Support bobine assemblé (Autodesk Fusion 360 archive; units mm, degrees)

design "Support bobine assemblé" references "Support bobine flanc gauche", "Support bobine flanc droit", "Support bobine base"
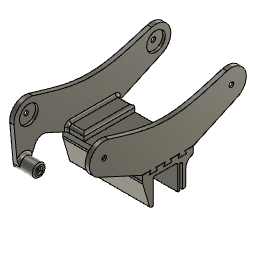
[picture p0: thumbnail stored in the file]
component_insert "Insertion d'un composant1"
component_insert "Insertion d'un composant2"
component_insert "Insertion d'un composant3"
joint "Assembler4" alignAngle 0 alignOffsetX 0 alignOffsetY 0 alignOffsetZ 0
joint "Assembler6" alignAngle 0 alignOffsetX 0 alignOffsetY 0 alignOffsetZ 0

design "Support bobine base"
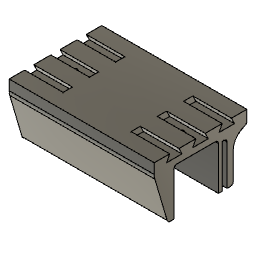
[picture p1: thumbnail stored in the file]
sketch "Esquisse1" plane through (0, 0, 0) normal (1, 0, 0) x axis (0, 1, 0)
  line L1 (21.2, 38) -> (-21.2, 38)
  line L2 (17.2, 0) -> (21.2, 0)
  line L3 (17.2, 28) -> (17.2, 0)
  line L4 (14, 0) -> (14, 28)
  line L5 (11.6, 0) -> (14, 0)
  line L6 (11.6, 30) -> (11.6, 0)
  line L7 (-17.2, 0) -> (-17.2, 30)
  line L8 (-21.2, 0) -> (-17.2, 0)
  line L9 (-21.2, 38) -> (-21.2, 0)
  line L10 (21.2, 38) -> (21.2, 0)
  line L11 (11.6, 30) -> (-17.2, 30)
  line L12 (17.2, 28) -> (14, 28)
  line L13 (-30, 38) -> (-21.2, 38)
  line L14 (30, 38) -> (21.2, 38)
  line L15 (27, 26) -> (21.2, 26)
  line L16 (30, 30) -> (30, 38)
  line L17 (21.2, 26) -> (30, 30)
  line L18 (-30, 30) -> (-30, 38)
  line L19 (-21.2, 0) -> (-30, 30)
  point P3 (21.2, 38)
  point P14 (21.2, 38)
  point P17 (21.2, 26)
  point P11 (-17.2, 30)
  point P12 (-17.2, 0)
  point P2 (-21.2, 38)
  point P13 (-21.2, 0)
  point P8 (14, 0)
  point P9 (11.6, 0)
  point P4 (21.2, 0)
  point P5 (17.2, 0)
  point P1 (0, 0)
  point P6 (17.2, 28)
  point P7 (14, 28)
  point P10 (11.6, 30)
  point P15 (-30, 38)
  point P16 (30, 38)
  point P19 (30, 30)
  point P20 (-30, 30)
  collinear L5 L8
  collinear L2 L8
  horizontal L1
  perpendicular L7 L11
  perpendicular L3 L12
  perpendicular L6 L11
  perpendicular L1 L9
  perpendicular L1 L10
  perpendicular L4 L12
  perpendicular L2 L10
  perpendicular L2 L3
  coincident P3 P14
  perpendicular L9 L13
  perpendicular L10 L14
  coincident L10 P17
  perpendicular L10 L15
  perpendicular L11 L18
  perpendicular L14 L16
  dimension "d3" distance P11 P12 = 30
  dimension "d4" distance P2 P13 = 38
  dimension "d5" distance P12 P13 = 4
  dimension "d6" distance P8 P9 = 2.4
  dimension "d7" distance P4 P5 = 4
  dimension "d8" distance P2 P3 = 42.4
  dimension "d9" distance P1 L1 = 38
  dimension "d10" distance P6 P7 = 3.2
  dimension "d11" distance P10 P11 = 28.8
  dimension "d12" distance P1 P13 = 21.2
  dimension "d21" distance P1 L12 = 28
  dimension "d24" distance P2 P15 = 8.8
  dimension "d25" distance P14 P16 = 8.8
  dimension "d26" distance L14 L15 = 12
  dimension "d59" distance L14 P19 = 8
  dimension "d64" distance P15 P20 = 8
extrude "Extrusion1" new body sketch "Esquisse1" profile of L1 L2 L3 L4 L5 L6 L7 L8 L9 L10 L11 L12 L13 L14 L16 L17 L18 L19 distance 47
sketch "Esquisse3" plane through (0, 11.6, 0) normal (0, -1, 0) x axis (1, 0, 0)
  line L1 (5, -2) -> (5, 30)
  line L2 (-33, -2) -> (-33, 30)
  line L3 (-47, -2) -> (-47, 30)
  line L4 (-33, 30) -> (-47, 30)
  line L5 (5, 30) -> (-14, 30)
  line L6 (-33, -2) -> (-47, -2)
  line L7 (5, -2) -> (-14, -2)
  line L8 (-14, -2) -> (-14, 30)
  line L9 (47, 38) -> (-47, 38)
  line L10 (-47, 0) -> (47, 0)
  line L11 (47, 0) -> (47, 30)
  line L12 (47, 30) -> (-47, 30)
  line L13 (47, 38) -> (47, 30)
  line L14 (-47, 38) -> (47, 38)
  line L15 (-47, 30) -> (-47, 38)
  line L16 (47, 0) -> (-47, 0)
  line L17 (47, 30) -> (47, 0)
  line L18 (-47, 30) -> (47, 30)
  line L19 (-47, 0) -> (-47, 30)
  point P3 (-14, 30)
  point P9 (-14, -2)
  point P6 (5, -2)
  point P8 (-33, -2)
  point P7 (-47, -2)
  coincident P3 L4
  perpendicular L2 L4
  perpendicular L3 L4
  perpendicular L1 L6
  coincident P9 L6
  collinear L4 L5
  collinear L6 L7
  perpendicular L7 L8
  dimension "d38" distance P6 P9 = 19
  dimension "d39" distance P8 P9 = 19
  dimension "d40" distance L4 L6 = 32
  dimension "d65" distance L4 L14 = 8
  dimension "d66" distance L1 L17 = 42
  dimension "d67" distance P7 P8 = 14
extrude "Extrusion2" cut sketch "Esquisse3" profile of L5 L1 L2 L3 L7 to an object
sketch "Esquisse5" plane through (0, 0, 0) normal (1, 0, 0) x axis (0, 1, 0)
  line L1 (21.2, 22.7263) -> (21.2, 2)
  line L2 (30, 38) -> (23.136, 28.6399)
  line L3 (-30, 38) -> (30, 38)
  line L4 (-21.5587, 1.5488) -> (-30, 38)
  line L5 (-17.2, 0) -> (-19.6102, 0)
  line L6 (-17.2, 28) -> (-17.2, 0)
  line L7 (9.6, 30) -> (-15.2, 30)
  line L8 (11.6, 0) -> (11.6, 28)
  line L9 (14, 0) -> (11.6, 0)
  line L10 (14, 28) -> (14, 0)
  line L11 (15.2, 28) -> (14, 28)
  line L12 (17.2, 0) -> (17.2, 26)
  line L13 (19.2, 0) -> (17.2, 0)
  line L14 (0, 38) -> (0, 0)
  line L15 (30, 34) -> (-30, 34)
  line L16 (-30, 38) -> (30, 38)
  line L17 (-3, 38) -> (-5, 34)
  line L18 (3, 38) -> (5, 34)
  line L19 (3, 38) -> (-3, 38)
  line L20 (5, 34) -> (-5, 34)
  line L21 (-20, 38) -> (-22, 34)
  line L22 (-14, 38) -> (-12, 34)
  line L23 (-12, 34) -> (-22, 34)
  line L24 (-14, 38) -> (-20, 38)
  line L25 (14, 38) -> (12, 34)
  line L26 (20, 38) -> (22, 34)
  line L27 (22, 34) -> (12, 34)
  line L28 (20, 38) -> (14, 38)
  line L29 (30, 38) -> (-30, 38)
  line L30 (-29.0737, 34) -> (27.0667, 34)
  arc A1 centre (19.2, 2) radius 2 clockwise from (21.2, 2) to (19.2, 0)
  arc A2 centre (31.2, 22.7263) radius 10 clockwise from (21.2, 22.7263) to (23.136, 28.6399)
  arc A3 centre (-19.6102, 2) radius 2 clockwise from (-19.6102, 0) to (-21.5587, 1.5488)
  arc A4 centre (-15.2, 28) radius 2 clockwise from (-17.2, 28) to (-15.2, 30)
  arc A5 centre (9.6, 28) radius 2 clockwise from (9.6, 30) to (11.6, 28)
  arc A6 centre (15.2, 26) radius 2 clockwise from (15.2, 28) to (17.2, 26)
  point P1 (0, 0)
  point P27 (0, 0)
  point P29 (-30, 34)
  point P32 (-30, 38)
  point P28 (0, 38)
  point P33 (-5, 34)
  point P34 (-3, 38)
  point P35 (5, 34)
  point P36 (3, 38)
  point P47 (27.0667, 34)
  point P48 (-29.0737, 34)
  coincident P1 P27
  perpendicular L3 L14
  horizontal L15
  equal L3 L15
  vertical P29 P32
  coincident P28 L16
  coincident L15 P33
  coincident L16 P34
  symmetric L14 P33 P35
  symmetric L14 P34 P36
  coincident L2 P47
  coincident L15 P47
  coincident L15 P48
  coincident L4 P48
  dimension "d48" distance L15 L16 = 4
  dimension "d50" distance P28 P34 = 3
  dimension "d51" distance P28 P33 = 5
  dimension "d54" R-Pattern1-uDistance = 17
  dimension "d55" R-Pattern1-vDistance = 0
extrude "Extrusion3" cut sketch "Esquisse5" profile of L3 L16 L17 L18 L19 L20 L21 L22 L23 L24 L25 L26 L27 L28 L29 L30 no distance stored
extrude "Extrusion4" add sketch "Esquisse5" profile of L3 L16 L17 L18 L19 L20 L21 L22 L23 L24 L25 L26 L27 L28 L29 L30 distance 22
fillet "Congé10" radius 2
fillet "Congé11" radius 10
sketch "Esquisse8" plane through (0, 0, 34) normal (0, 0, 1) x axis (-1, 0, 0)
  line L1 (22, -5) -> (22, 5)
  line L2 (47, -5) -> (22, -5)
  line L3 (47, 5) -> (47, -5)
  line L4 (22, 5) -> (47, 5)
  line L5 (22, -20) -> (47, -20)
  line L6 (22, -14) -> (22, -20)
  line L7 (47, -14) -> (22, -14)
  line L8 (47, -3) -> (47, -14)
  line L9 (22, -3) -> (47, -3)
  line L10 (22, 3) -> (22, -3)
  line L11 (47, 3) -> (22, 3)
  line L12 (47, 14) -> (47, 3)
  line L13 (22, 14) -> (47, 14)
  line L14 (22, 20) -> (22, 14)
  line L15 (47, 20) -> (22, 20)
  line L16 (47, 30) -> (47, 20)
  line L17 (-47, 30) -> (47, 30)
  line L18 (-47, 20) -> (-47, 30)
  line L19 (-22, 20) -> (-47, 20)
  line L20 (-22, 14) -> (-22, 20)
  line L21 (-47, 14) -> (-22, 14)
  line L22 (-47, 3) -> (-47, 14)
  line L23 (-22, 3) -> (-47, 3)
  line L24 (-22, -3) -> (-22, 3)
  line L25 (-47, -3) -> (-22, -3)
  line L26 (-47, -14) -> (-47, -3)
  line L27 (-22, -14) -> (-47, -14)
  line L28 (-22, -20) -> (-22, -14)
  line L29 (-47, -20) -> (-22, -20)
  line L30 (-47, -30) -> (-47, -20)
  line L31 (47, -30) -> (-47, -30)
  line L32 (47, -20) -> (47, -30)
  circle C1 centre (34.5, 0) radius 1.7
  circle C2 centre (-34.5, 0) radius 1.7
  point P34 (34.5, 0)
  point P35 (-34.5, 0)
  dimension "d75" diameter C1 = 3.4
  dimension "d76" diameter C2 = 3.4
  dimension "d77" distance L3 P34 = 12.5
  dimension "d78" distance L31 P34 = 30
  dimension "d79" distance L22 P35 = 12.5
  dimension "d80" distance L31 P35 = 30
extrude "Extrusion5" cut sketch "Esquisse8" profile of C1 C2 no distance stored
sketch "Esquisse9" plane through (0, 0, 30) normal (0, 0, -1) x axis (1, 0, 0)
  line L1 (47, -9.6) -> (5, -9.6)
  line L2 (47, 15.2) -> (47, -9.6)
  line L3 (-47, 15.2) -> (47, 15.2)
  line L4 (-47, -14) -> (-47, 15.2)
  line L5 (-14, -14) -> (-14, -9.6)
  line L6 (5, -14) -> (-14, -14)
  line L7 (5, -9.6) -> (5, -14)
  line L8 (-33, -14) -> (-47, -14)
  line L9 (-33, -9.6) -> (-33, -14)
  line L10 (-14, -9.6) -> (-33, -9.6)
  circle C1 centre (-34.5, 0) radius 1.7
  circle C2 centre (34.5, 0) radius 1.7
  circle C3 centre (34.5, 0) radius 3.25
  circle C4 centre (-34.5, 0) radius 3.25
  concentric C2 C3
  concentric C1 C4
  dimension "d82" diameter C3 = 6.5
  dimension "d83" diameter C4 = 6.5
extrude "Extrusion6" cut sketch "Esquisse9" profile of C1 C2 C3 C4 against normal blind 2
sketch "Esquisse10" plane through (0, 21.2, 0) normal (0, 1, 0) x axis (-1, 0, 0)
  line L1 (-47, 19.5609) -> (47, 19.5609)
  line L2 (-47, 2) -> (-47, 19.5609)
  line L3 (47, 2) -> (-47, 2)
  line L4 (47, 19.5609) -> (47, 2)
  line L5 (36, -2) -> (28, -2)
  line L6 (36, 13) -> (36, -2)
  line L7 (28, 13) -> (36, 13)
  line L8 (28, -2) -> (28, 13)
  line L9 (47, 0) -> (-47, 0)
  line L10 (47, 2) -> (47, 19.5609)
  point P6 (28, -2)
  point P7 (36, -2)
  point P8 (36, 13)
  horizontal L5
  vertical L6
  horizontal L7
  vertical L8
  dimension "d86" distance P6 P7 = 8
  dimension "d87" distance P7 P8 = 15
  dimension "d88" distance L7 L9 = 13
  dimension "d89" distance L6 L10 = 11
extrude "Extrusion7" cut sketch "Esquisse10" profile of L3 L5 L6 L7 L8 L9 to an object

design "Support bobine flanc gauche"
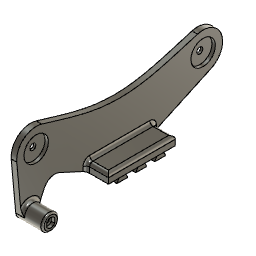
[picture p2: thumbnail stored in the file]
sketch "Esquisse1" plane through (0, 0, 0) normal (1, 0, 0) x axis (0, 1, 0)
  line L1 (30, 3.8) -> (-30, 3.8)
  line L2 (0, 13.257) -> (0, 0)
  line L3 (-4.9, 0) -> (-2.9, 3.8)
  line L4 (4.9, 0) -> (2.9, 3.8)
  line L5 (-21.9, 0) -> (-19.9, 3.8)
  line L6 (-12.1, 0) -> (-14.1, 3.8)
  line L7 (12.1, 0) -> (14.1, 3.8)
  line L8 (21.9, 0) -> (19.9, 3.8)
  line L9 (-12.1, 0) -> (-21.9, 0)
  line L10 (4.9, 0) -> (-4.9, 0)
  line L11 (21.9, 0) -> (12.1, 0)
  line L12 (75, 43.8) -> (-75, 43.8)
  line L13 (82.3227, 27.9057) -> (30, 3.8)
  line L14 (-82.3227, 27.9057) -> (-30, 3.8)
  curve K1 (70.0046, 60.5719) -> (-70.0046, 60.5719)
  curve K2 (14.2216, 45.8) -> (-14.2216, 45.8)
  line L15 (-88.3648, -1.8881) -> (-92.4262, 42.1945)
  line L16 (-63.2728, 19.1292) -> (-74.0846, -4.3383)
  line L17 (-30, 11.8) -> (-30, 3.8)
  line L18 (30, 11.8) -> (30, 3.8)
  line L19 (30, 11.8) -> (-30, 11.8)
  circle C1 centre (-75, 43.8) radius 2.7
  circle C2 centre (-75, 43.8) radius 8
  circle C3 centre (-75, 43.8) radius 17.5
  circle C4 centre (75, 43.8) radius 2.7
  circle C5 centre (75, 43.8) radius 8
  circle C6 centre (75, 43.8) radius 17.5
  circle C7 centre (0, 121.511) radius 100
  circle C8 centre (-80.8964, -1.2) radius 1.7
  circle C9 centre (-80.8964, -1.2) radius 7.5
  circle C10 centre (-80.8964, -1.2) radius 3.5
  point P1 (0, 0)
  point P4 (0, 0)
  point P6 (-2.9, 3.8)
  point P7 (-4.9, 0)
  point P8 (2.9, 3.8)
  point P9 (4.9, 0)
  point P18 (-75, 43.8)
  point P20 (-75, 43.8)
  point P27 (82.3227, 27.9057)
  point P28 (-82.3227, 27.9057)
  point P29 (-70.0046, 60.5719)
  point P31 (70.0046, 60.5719)
  point P30 (0, 45.8)
  point P36 (-92.4262, 42.1945)
  point P37 (-88.3648, -1.8881)
  point P38 (-74.0846, -4.3383)
  point P39 (-63.2728, 19.1292)
  point P19 (75, 43.8)
  point P35 (-80.8964, -1.2)
  point P2 (-30, 3.8)
  point P3 (30, 3.8)
  horizontal L9
  parallel L1 L9
  coincident P1 P4
  perpendicular L2 L9
  coincident L1 P6
  coincident P7 L9
  symmetric L2 P6 P8
  symmetric L2 P7 P9
  coincident P1 L9
  collinear L9 L10
  collinear L10 L11
  horizontal L12
  coincident P18 P20
  concentric C1 C2
  concentric C2 C3
  symmetric L2 C1 C4
  symmetric L2 C2 C5
  symmetric L2 C3 C6
  tangent C2 C7
  tangent C5 C7
  coincident C6 P27
  tangent C6 L13
  coincident C3 P28
  tangent C3 L14
  coincident C3 P29
  coincident C6 P31
  tangent C6 K1
  tangent C3 K1
  midpoint P30 K2
  horizontal K2
  concentric C8 C9
  coincident C3 P36
  coincident C9 P37
  coincident C9 P38
  coincident L14 P39
  perpendicular L14 L16
  tangent C9 L16
  tangent C9 L15
  tangent C3 L15
  perpendicular L1 L17
  perpendicular L1 L18
  concentric C8 C10
  dimension "d2" distance L1 L9 = 3.8
  dimension "d3" distance L2 P6 = 2.9
  dimension "d4" distance L2 P7 = 4.9
  dimension "d9" distance P18 P19 = 150
  dimension "d10" distance P1 P18 = 75
  dimension "d11" diameter C1 = 5.4
  dimension "d12" diameter C2 = 16
  dimension "d13" diameter C3 = 35
  dimension "d14" diameter C7 = 200
  dimension "d15" distance L1 L12 = 40
  dimension "d16" distance L1 P30 = 42
  dimension "d17" diameter C8 = 3.4
  dimension "d19" diameter C9 = 15
  dimension "d20" distance L1 P35 = 5
  dimension "d23" distance P2 P3 = 60
  dimension "d25" distance P1 L17 = 30
  dimension "d26" distance L1 L19 = 8
  dimension "d27" angle L14 L15 = 60
  dimension "d48" diameter C10 = 7
  dimension "d7" R-Pattern1-uDistance = 17
  dimension "d8" R-Pattern1-vDistance = 0
extrude "Extrusion1" new body sketch "Esquisse1" profile of C1 C3 C4 C6 L13 L14 K1 C8 C9 L15 L16 L17 L18 L19 along normal blind 5
extrude "Extrusion2" add sketch "Esquisse1" profile of L1 L17 L18 L19 along normal blind 25
sketch "Esquisse2" plane through (5, 0, 0) normal (1, 0, 0) x axis (0, 1, 0)
  line L1 (-30, 11.8) -> (-30, 3.8)
  line L2 (30, 11.8) -> (-30, 11.8)
  line L3 (30, 3.8) -> (30, 11.8)
  line L4 (82.3227, 27.9057) -> (30, 3.8)
  curve K1 (-70.0046, 60.5719) -> (70.0046, 60.5719)
  line L5 (-88.3648, -1.8881) -> (-92.4262, 42.1945)
  line L6 (-63.2728, 19.1292) -> (-74.0846, -4.3383)
  line L7 (-30, 3.8) -> (-63.2728, 19.1292)
  circle C1 centre (-80.8964, -1.2) radius 1.7
  circle C2 centre (-75, 43.8) radius 2.7
  circle C3 centre (75, 43.8) radius 2.7
  arc A1 centre (75, 43.8) radius 17.5 clockwise from (70.0046, 60.5719) to (82.3227, 27.9057)
  arc A2 centre (-75, 43.8) radius 17.5 clockwise from (-92.4262, 42.1945) to (-70.0046, 60.5719)
  arc A3 centre (-80.8964, -1.2) radius 7.5 clockwise from (-74.0846, -4.3383) to (-88.3648, -1.8881)
  circle C4 centre (-75, 43.8) radius 11
  circle C5 centre (75, 43.8) radius 11
  circle C6 centre (-80.8964, -1.2) radius 7.5
  concentric C2 C4
  concentric C3 C5
  concentric C1 C6
  dimension "d34" diameter C4 = 22
  dimension "d35" diameter C5 = 22
  dimension "d38" diameter C6 = 15
extrude "Extrusion3" cut sketch "Esquisse2" profile of C2 C3 C4 C5 against normal blind 3
extrude "Extrusion4" add sketch "Esquisse2" profile of C1 A3 C6 along normal blind 19
sketch "Esquisse3" plane through (24, 0, 0) normal (1, 0, 0) x axis (0, 1, 0)
  line L1 (-84.3962, 0.9358) -> (-84.3962, -3.3358)
  line L2 (-77.3962, -3.335) -> (-77.3962, 0.935)
  circle C1 centre (-80.8964, -1.2) radius 1.7
  circle C2 centre (-80.8964, -1.2) radius 7.5
  circle C3 centre (-80.8964, -1.2) radius 4.1
  point P2 (-80.8964, -1.2)
  point P4 (-80.8964, -1.2)
  point P5 (-84.3962, -3.3358)
  point P6 (-84.3962, 0.9358)
  point P7 (-77.3962, 0.935)
  point P8 (-77.3962, -3.335)
  concentric C1 C3
  parallel L1 L2
  coincident P2 P4
  coincident C3 P5
  coincident C3 P6
  coincident C3 P7
  coincident C3 P8
  vertical L1
  dimension "d41" diameter C3 = 8.2
  dimension "d44" distance L1 L2 = 7
  dimension "d45" distance P7 P8 = 4.27
extrude "Extrusion5" cut sketch "Esquisse3" profile of C1 C3 L1 L2 against normal blind 3
extrude "Extrusion6" cut sketch "Esquisse1" profile of C8 C10 along normal blind 17.5
fillet "Congé2" radius 1.5
fillet "Congé3" radius 3
fillet "Congé4" radius 10
fillet "Congé5" radius 3
fillet "Congé6" radius 3
extrude "Extrusion8" add sketch "Esquisse1" profile of L11 L1 L3 L4 L5 L6 L7 L8 along normal blind 24.5
sketch "Esquisse5" plane through (0, 0, 0) normal (0, 0, -1) x axis (1, 0, 0)
  line L1 (0, -4.9) -> (0, 4.9)
  line L2 (24.5, -4.9) -> (0, -4.9)
  line L3 (24.5, 4.9) -> (24.5, -4.9)
  line L4 (0, 4.9) -> (24.5, 4.9)
  circle C1 centre (12.5, 0) radius 1.4
  point P6 (12.5, 0)
  dimension "d68" diameter C1 = 2.8
  dimension "d69" distance L1 P6 = 12.5
  dimension "d70" distance L4 P6 = 4.9
extrude "Extrusion9" cut sketch "Esquisse5" profile of C1 against normal blind 10

design "Support bobine flanc droit"
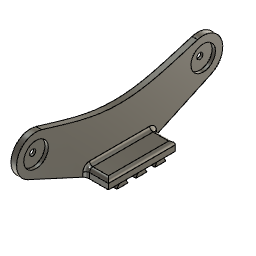
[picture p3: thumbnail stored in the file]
sketch "Esquisse1" plane through (0, 0, 0) normal (1, 0, 0) x axis (0, 1, 0)
  line L1 (30, 3.8) -> (-30, 3.8)
  line L2 (0, 13.257) -> (0, 0)
  line L3 (-4.9, 0) -> (-2.9, 3.8)
  line L4 (4.9, 0) -> (2.9, 3.8)
  line L5 (-21.9, 0) -> (-19.9, 3.8)
  line L6 (-12.1, 0) -> (-14.1, 3.8)
  line L7 (12.1, 0) -> (14.1, 3.8)
  line L8 (21.9, 0) -> (19.9, 3.8)
  line L9 (-12.1, 0) -> (-21.9, 0)
  line L10 (4.9, 0) -> (-4.9, 0)
  line L11 (21.9, 0) -> (12.1, 0)
  line L12 (75, 43.8) -> (-75, 43.8)
  line L13 (82.3227, 27.9057) -> (30, 3.8)
  line L14 (-82.3227, 27.9057) -> (-30, 3.8)
  curve K1 (70.0046, 60.5719) -> (-70.0046, 60.5719)
  curve K2 (14.2216, 45.8) -> (-14.2216, 45.8)
  line L15 (-30, 11.8) -> (-30, 3.8)
  line L16 (30, 11.8) -> (30, 3.8)
  line L17 (30, 11.8) -> (-30, 11.8)
  circle C1 centre (-75, 43.8) radius 2.7
  circle C2 centre (-75, 43.8) radius 8
  circle C3 centre (-75, 43.8) radius 17.5
  circle C4 centre (75, 43.8) radius 2.7
  circle C5 centre (75, 43.8) radius 8
  circle C6 centre (75, 43.8) radius 17.5
  circle C7 centre (0, 121.511) radius 100
  point P1 (0, 0)
  point P4 (0, 0)
  point P6 (-2.9, 3.8)
  point P7 (-4.9, 0)
  point P8 (2.9, 3.8)
  point P9 (4.9, 0)
  point P18 (-75, 43.8)
  point P20 (-75, 43.8)
  point P27 (82.3227, 27.9057)
  point P28 (-82.3227, 27.9057)
  point P29 (-70.0046, 60.5719)
  point P31 (70.0046, 60.5719)
  point P30 (0, 45.8)
  point P19 (75, 43.8)
  point P2 (-30, 3.8)
  point P3 (30, 3.8)
  horizontal L9
  parallel L1 L9
  coincident P1 P4
  perpendicular L2 L9
  coincident L1 P6
  coincident P7 L9
  symmetric L2 P6 P8
  symmetric L2 P7 P9
  coincident P1 L9
  collinear L9 L10
  collinear L10 L11
  horizontal L12
  coincident P18 P20
  concentric C1 C2
  concentric C2 C3
  symmetric L2 C1 C4
  symmetric L2 C2 C5
  symmetric L2 C3 C6
  tangent C2 C7
  tangent C5 C7
  coincident C6 P27
  tangent C6 L13
  coincident C3 P28
  tangent C3 L14
  coincident C3 P29
  coincident C6 P31
  tangent C6 K1
  tangent C3 K1
  midpoint P30 K2
  horizontal K2
  perpendicular L1 L15
  perpendicular L1 L16
  dimension "d2" distance L1 L9 = 3.8
  dimension "d3" distance L2 P6 = 2.9
  dimension "d4" distance L2 P7 = 4.9
  dimension "d9" distance P18 P19 = 150
  dimension "d10" distance P1 P18 = 75
  dimension "d11" diameter C1 = 5.4
  dimension "d12" diameter C2 = 16
  dimension "d13" diameter C3 = 35
  dimension "d14" diameter C7 = 200
  dimension "d15" distance L1 L12 = 40
  dimension "d16" distance L1 P30 = 42
  dimension "d23" distance P2 P3 = 60
  dimension "d25" distance P1 L15 = 30
  dimension "d26" distance L1 L17 = 8
  dimension "d7" R-Pattern1-uDistance = 17
  dimension "d8" R-Pattern1-vDistance = 0
extrude "Extrusion1" new body sketch "Esquisse1" profile of C1 C3 C4 C6 L13 L14 K1 L15 L16 L17 along normal blind 5
extrude "Extrusion2" add sketch "Esquisse1" profile of L1 L15 L16 L17 along normal blind 25
sketch "Esquisse2" plane through (5, 0, 0) normal (1, 0, 0) x axis (0, 1, 0)
  line L1 (-30, 11.8) -> (-30, 3.8)
  line L2 (30, 11.8) -> (-30, 11.8)
  line L3 (30, 3.8) -> (30, 11.8)
  line L4 (82.3227, 27.9057) -> (30, 3.8)
  curve K1 (-70.0046, 60.5719) -> (70.0046, 60.5719)
  line L5 (-30, 3.8) -> (-82.3227, 27.9057)
  circle C1 centre (-75, 43.8) radius 2.7
  circle C2 centre (75, 43.8) radius 2.7
  arc A1 centre (75, 43.8) radius 17.5 clockwise from (70.0046, 60.5719) to (82.3227, 27.9057)
  arc A2 centre (-75, 43.8) radius 17.5 clockwise from (-82.3227, 27.9057) to (-70.0046, 60.5719)
  circle C3 centre (-75, 43.8) radius 11
  circle C4 centre (75, 43.8) radius 11
  concentric C1 C3
  concentric C2 C4
  dimension "d34" diameter C3 = 22
  dimension "d35" diameter C4 = 22
extrude "Extrusion3" cut sketch "Esquisse2" profile of C1 C2 C3 C4 against normal blind 3
fillet "Congé2" radius 3
fillet "Congé3" radius 3
extrude "Extrusion8" add sketch "Esquisse1" profile of L11 L1 L3 L4 L5 L6 L7 L8 along normal blind 24.5
sketch "Esquisse6" plane through (0, 0, 0) normal (0, 0, -1) x axis (1, 0, 0)
  line L1 (0, -4.9) -> (0, 4.9)
  line L2 (24.5, -4.9) -> (0, -4.9)
  line L3 (24.5, 4.9) -> (24.5, -4.9)
  line L4 (0, 4.9) -> (24.5, 4.9)
  line L5 (0, -4.9) -> (0, 4.9)
  circle C1 centre (12.5, 0) radius 1.4
  point P6 (12.5, 0)
  dimension "d62" diameter C1 = 2.8
  dimension "d63" distance L4 P6 = 4.9
  dimension "d64" distance P6 L5 = 12.5
extrude "Extrusion9" cut sketch "Esquisse6" profile of C1 against normal blind 10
